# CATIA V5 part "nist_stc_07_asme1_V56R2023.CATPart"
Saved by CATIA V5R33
Part number: nist_stc_07_asme1
Nomenclature: nist_ftc_07_asme1
Source: Unknown
Bounding box of the stored display mesh (mm): x -155.803 to 155.803, y -123.19 to 12.7, z -111.353 to 111.353
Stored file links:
  C:\Users\rla3\OneDrive - NIST\STEP\NIST Test Models\STC\NIST_STC\07\V5\nist_stc_07_asme1_V56R2023-20231206.CATPart
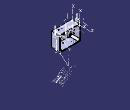
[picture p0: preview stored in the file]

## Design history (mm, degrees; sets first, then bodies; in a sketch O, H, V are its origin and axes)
TTRSSet1
f4a2d38f3ddc11d3a929006094b99c4b_11 "CATTPSSet"
Set1 "MBD_A"
  Plane1: type Offset, RefPlane face of Solid1, Offset 0, reversed
  Intersect1: ToIntersect1 edge [ZX plane of AxisSystem3 | YZ plane of AxisSystem3], ToIntersect2 Plane1
  AxisSystem1 "DBC": origin (-142.875, -104.14, 98.425), X (0, 0, 1), Y (1, 0, 0), Z (0, 1, 0)
Set2 "MBD_B"
  Sketch1 on face of Solid1, origin (0, 12.7, 0), H (-1, 0, 0), V (0, 0, 1)
    arc A1 centre (142.875, 98.425) radius 53.34 from (94.1938, 120.2262) to (117.2764, 145.221) ccw
    point P1 (117.2764, 145.221)
    point P2 (94.1938, 120.2262)
    reference projected line E2 (117.8859, 144.1068) -> (116.6669, 146.3352) from edge of Fill1
    reference projected line E3 (93.0347, 120.7453) -> (95.3528, 119.7071) from edge of Fill1
    radius A1 = 53.34
    distance P1 E2 = 0
    distance P2 E3 = 0
  Sketch2 on face of Solid1, origin (0, 12.7, 0), H (-1, 0, 0), V (0, 0, 1)
    reference projected point E1 (142.875, 98.425) from vertex [YZ plane of AxisSystem3 | ZX plane of AxisSystem3 | XY plane of AxisSystem3]
    point P1 (93.0347, 120.7453)
    point P2 (116.6669, 146.3352)
    point P3 (117.5086, 145.3842)
    point P4 (94.1938, 120.2262)
    point P5 (117.8859, 144.1068)
    line L1 (117.8859, 144.1068) -> (116.6669, 146.3352)
    point P6 (95.3528, 119.7071)
    line L2 (95.3528, 119.7071) -> (93.0347, 120.7453)
    line L3 (93.0347, 120.7453) -> (97.0262, 125.6839)
    point P7 (97.0262, 125.6839)
    line L4 (97.0262, 125.6839) -> (95.3528, 119.7071)
    line L5 (116.6669, 146.3352) -> (112.0609, 141.964)
    point P8 (112.0609, 141.964)
    line L6 (117.8859, 144.1068) -> (112.0609, 141.964)
    construction line L7 (142.875, 98.425) -> (112.3984, 154.1383)
    point P9 (112.3984, 154.1383)
    distance P3 P2 = 1.27
    length L1 = 2.54
    distance P1 P4 = 1.27
    length L2 = 2.54
    length L3 = 6.35
    length L5 = 6.35
    distance E1 P7 = 53.34
    distance E1 P8 = 53.34
    distance P5 E1 = 52.07
    distance P6 E1 = 52.07
    coincidence: E1 L2, E1 L1, L1 L7, P9 L1
    fix: L2
  Fill1: Boundary Sketch2
  Plane2: type Offset, RefPlane face of Solid1, Offset 0, reversed
  Intersect2: ToIntersect1 edge [ZX plane of AxisSystem3 | YZ plane of AxisSystem3], ToIntersect2 Plane2
  AxisSystem2 "EBC": origin (-142.875, -123.19, 98.425), X (0, 0, -1), Y (1, 0, 0), Z (0, -1, 0)
Set3 "MBD_ABCD"
  AxisSystem3 "ABC": origin (-142.875, 12.7, 98.425), X (0, 0, 1), Y (285.75, 0, 0), Z (0, 1, 0)
Body1 "Solid1" (main body)
  Solid1: solid without history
